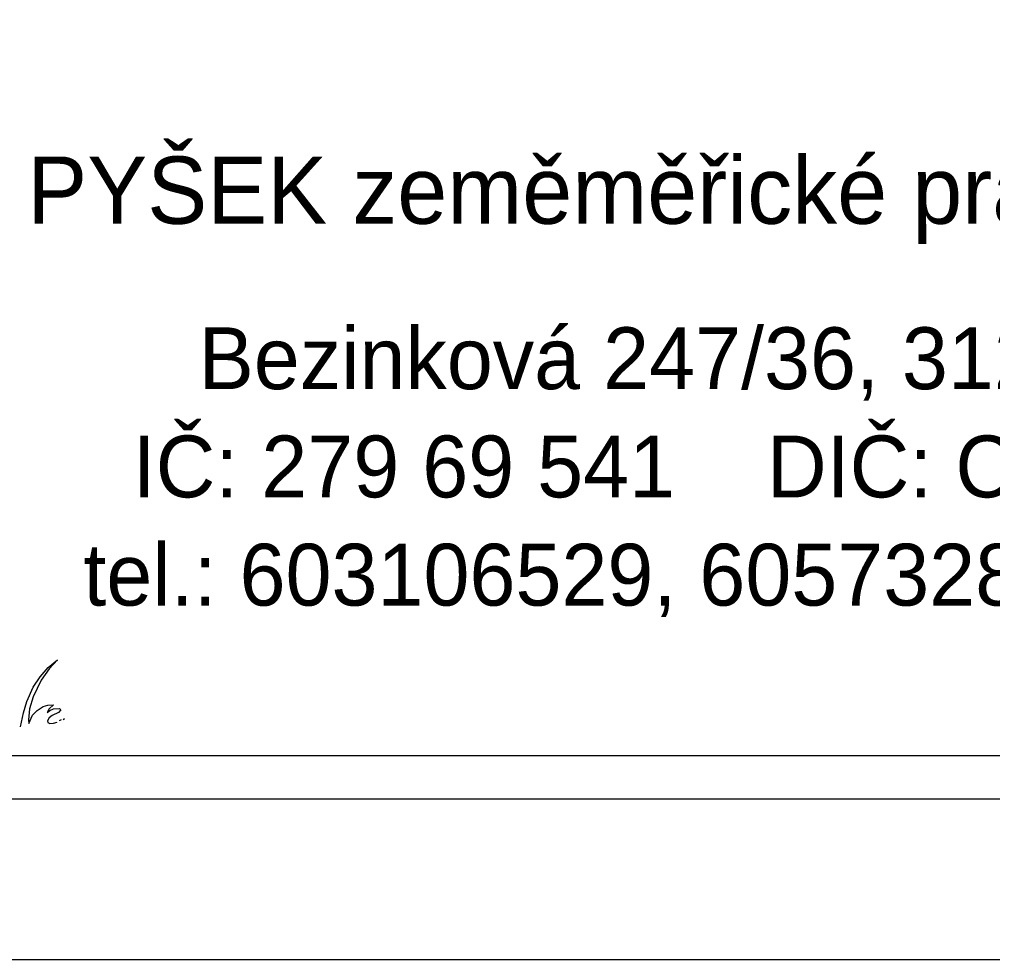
# Model space of a CAD drawing. Extents: x -836402.9 to -836350.7, y -1070439.4 to -1070369.1.
# Drawn here: x -836365.63 to -836358.94, y -1070439.38 to -1070432.92 of the extents above; entities that cross this region are included whole.
import ezdxf

# ---------------------------------------------------------------- set-up
doc = ezdxf.new("R2010")
doc.units = 0
doc.layers.add('razítko rámy', color=7, linetype='Continuous')
doc.layers.add('Vrstva 40', color=7, linetype='Continuous')

msp = doc.modelspace()

# ---------------------------------------------------------------- linework, layer by layer
at = {"layer": 'razítko rámy'}
for p, q in [((-836365.4314, -1070437.3677), (-836365.368, -1070437.3161)), ((-836365.368, -1070437.3161), (-836365.4255, -1070437.3783)), ((-836365.4877, -1070437.4335), (-836365.4314, -1070437.3677)), ((-836365.4255, -1070437.3783), (-836365.4807, -1070437.4558)), ((-836365.4807, -1070437.4558), (-836365.5358, -1070437.5697)), ((-836365.5347, -1070437.5039), (-836365.4877, -1070437.4335)), ((-836365.5781, -1070437.6014), (-836365.5347, -1070437.5039)), ((-836365.6027, -1070437.6812), (-836365.5781, -1070437.6014)), ((-836365.5358, -1070437.5697), (-836365.5605, -1070437.6518)), ((-836365.6215, -1070437.7763), (-836365.6027, -1070437.6812)), ((-836365.5605, -1070437.6518), (-836365.5675, -1070437.7282)), ((-836365.5393, -1070437.6953), (-836365.5088, -1070437.6636)), ((-836365.5088, -1070437.6636), (-836365.4666, -1070437.6366)), ((-836365.4666, -1070437.6366), (-836365.4349, -1070437.6284)), ((-836365.4243, -1070437.6518), (-836365.4396, -1070437.6777)), ((-836365.4396, -1070437.6777), (-836365.4197, -1070437.6648)), ((-836365.4349, -1070437.6284), (-836365.395, -1070437.626)), ((-836365.395, -1070437.626), (-836365.4243, -1070437.6518)), ((-836365.4197, -1070437.6648), (-836365.395, -1070437.6518)), ((-836365.3622, -1070437.6788), (-836365.4044, -1070437.6988)), ((-836365.395, -1070437.6518), (-836365.3551, -1070437.6495)), ((-836365.3457, -1070437.6601), (-836365.3622, -1070437.6788)), ((-836365.3551, -1070437.6495), (-836365.3457, -1070437.6601)), ((-836365.5675, -1070437.7282), (-836365.564, -1070437.7528)), ((-836365.564, -1070437.7528), (-836365.5393, -1070437.6953)), ((-836365.4243, -1070437.7152), (-836365.4361, -1070437.7364)), ((-836365.4361, -1070437.7364), (-836365.4349, -1070437.7469)), ((-836365.4349, -1070437.7469), (-836365.4208, -1070437.7528)), ((-836365.4044, -1070437.6988), (-836365.4243, -1070437.7152)), ((-836365.4208, -1070437.7528), (-836365.395, -1070437.7505)), ((-836365.395, -1070437.7505), (-836365.3704, -1070437.7446)), ((-836365.3434, -1070437.7293), (-836365.3575, -1070437.7364)), ((-836365.3281, -1070437.7258), (-836365.3199, -1070437.7199))]:
    msp.add_line(p, q, dxfattribs=at)
for points in [[(-836401.0452, -1070420.6652), (-836356.4524, -1070420.6652), (-836356.4524, -1070438.2735), (-836401.0452, -1070438.2735)], [(-836400.7473, -1070420.9631), (-836356.7503, -1070420.9631), (-836356.7503, -1070437.9756), (-836400.7473, -1070437.9756)]]:
    msp.add_lwpolyline(points, close=True, dxfattribs=at)
at = {"layer": 'Vrstva 40'}
msp.add_line((-836402.8516, -1070439.3758), (-836353.1309, -1070439.3758), dxfattribs=at)

# ---------------------------------------------------------------- texts
at = {"layer": 'razítko rámy'}
for s, height, p in [('PYŠEK zeměměřické práce, s.r.o.', 0.4625, (-836365.5761, -1070434.3194)), ('Bezinková 247/36, 312 00 Plzeň', 0.425, (-836364.3974, -1070435.4559)), ('IČ: 279 69 541    DIČ: CZ 279 69 541', 0.425, (-836364.8509, -1070436.1996)), ('tel.: 603106529, 605732874, 737747422', 0.425, (-836365.1903, -1070436.9434))]:
    msp.add_text(s, height=height, dxfattribs=at).set_placement(p)

doc.saveas('drawing.dxf')
